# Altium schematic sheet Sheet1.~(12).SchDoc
size A; SheetNumber: 1; SheetTotal: 1
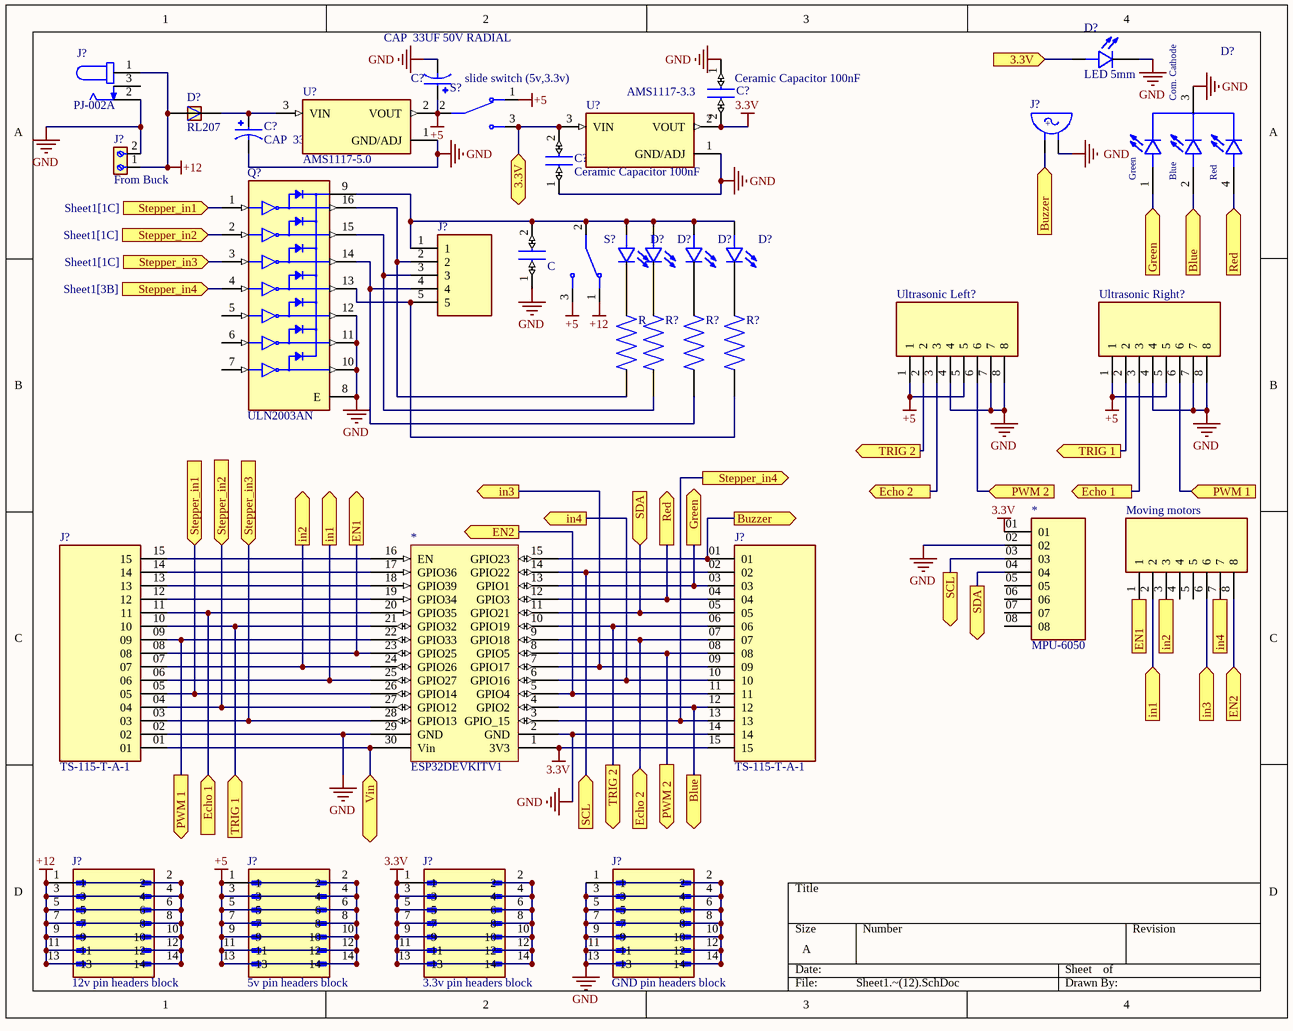
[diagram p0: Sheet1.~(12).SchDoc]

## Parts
(Parts that share a designator on the sheet are numbered #1, #2 ... from top to bottom, then left to right.)
*#1  MPU-6050  [MPU-6050]
*#2  ESP32DEVKITV1  [ESP32DEVKITV1]
C  Ceramic Capacitor 100nF  [C320C]  (value not drawn)
C?#1  Ceramic Capacitor 100nF  [C320C]
C?#2  CAP  33UF 50V RADIAL  [CAP  33UF 50V RADIAL]
C?#3  CAP  33UF 50V RADIAL  [CAP  33UF 50V RADIAL]
C?#4  Ceramic Capacitor 100nF  [C320C]
D?#1  LED 5mm  [LED 5mm]
D?#2  RL207  [DIOAD1300W80L670D310]
D?#3  common cathode  [LED RGB 5mm]  (value not drawn)
D?#4  LED 5mm  [LED 5mm]  (value not drawn)
D?#5  LED 5mm  [LED 5mm]  (value not drawn)
D?#6  LED 5mm  [LED 5mm]  (value not drawn)
D?#7  LED 5mm  [LED 5mm]  (value not drawn)
J?#1  PJ-002A  [CUI_PJ-002A]
J?#2  WST-1205S  [WST-1205S]  (value not drawn)
J?#3  From Buck  [691213510002]
J?#4  Pin hreader 5 pins  [Pin hreader 5 pins]  (value not drawn)
J?#5  TS-115-T-A-1  [SAMTEC_TS-115-T-A-1]
J?#6  TS-115-T-A-1  [SAMTEC_TS-115-T-A-1]
J?#7  12v pin headers block  [AMPHENOL_52601-S14-4LF]
J?#8  5v pin headers block  [AMPHENOL_52601-S14-4LF]
J?#9  3.3v pin headers block  [AMPHENOL_52601-S14-4LF]
J?#10  GND pin headers block  [AMPHENOL_52601-S14-4LF]
Moving_motors  Pin header female block 8 pin  [Pin header female block 8 pin]  (value not drawn)
Q?  ULN2003AN  [DIP794W45P254L1969H508Q16]
R  Resistor  [RESAD700W45L350D185]  (value not drawn)
R?#1  Resistor  [RESAD700W45L350D185]  (value not drawn)
R?#2  Resistor  [RESAD700W45L350D185]  (value not drawn)
R?#3  Resistor  [RESAD700W45L350D185]  (value not drawn)
S?#1  slide switch (5v,3.3v)  [SW_EG1206]
S?#2  Slide switch  [Slide switch]  (value not drawn)
U?#1  AMS1117-5.0  [SOT229P700X180-4N]
U?#2  AMS1117-3.3  [SOT229P700X180-4N]
Ultrasonic_Left?  Pin header female block 8 pin  [Pin header female block 8 pin]  (value not drawn)
Ultrasonic_Right?  Pin header female block 8 pin  [Pin header female block 8 pin]  (value not drawn)

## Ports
3.3V (bidir, see Sheet1[4A]), 3.3V (in, see Sheet1[2A]), Blue (in, see Sheet1[3D]), Blue (out, see Sheet1[4B]), Buzzer (in, see Sheet1[3C]), Buzzer (out, see Sheet1[4A]), Echo 1 (in, see Sheet1[4B]), Echo 1 (out, see Sheet1[1D]), Echo 2 (in, see Sheet1[3B]), Echo 2 (out, see Sheet1[2D]), EN1 (in, see Sheet1[2C]), EN1 (out, see Sheet1[4C]), EN2 (in, see Sheet1[2C]), EN2 (out, see Sheet1[4C]), Green (in, see Sheet1[3C]), Green (out, see Sheet1[4B]), in1 (in, see Sheet1[2C]), in1 (out, see Sheet1[4C]), in2 (in, see Sheet1[1C]), in2 (out, see Sheet1[4C]), in3 (in, see Sheet1[2B]), in3 (out, see Sheet1[4C]), in4 (in, see Sheet1[2C]), in4 (out, see Sheet1[4C]), PWM 1 (in, see Sheet1[1D]), PWM 1 (out, see Sheet1[4B]), PWM 2 (in, see Sheet1[3D]), PWM 2 (out, see Sheet1[4B]), Red (in, see Sheet1[3C]), Red (out, see Sheet1[4B]), SCL (in, see Sheet1[3C]), SCL (out, see Sheet1[2D]), SDA (in, see Sheet1[4C]), SDA (out, see Sheet1[2C]), Stepper_in1 (in, see Sheet1[1A]), Stepper_in1 (in, see Sheet1[1C]), Stepper_in2 (in, see Sheet1[1A]), Stepper_in2 (in, see Sheet1[1C]), Stepper_in3 (in, see Sheet1[1B]), Stepper_in3 (in, see Sheet1[1C]), Stepper_in4 (in, see Sheet1[3B]), Stepper_in4 (out, see Sheet1[1B]), TRIG 1 (in, see Sheet1[4B]), TRIG 1 (out, see Sheet1[1D]), TRIG 2 (out, see Sheet1[2D]), TRIG 2 (out, see Sheet1[3B]), Vin (bidir)

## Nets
3.3V: *#1.01 *#2.1(3V3) C?#1.2 J?#6.15 J?#9.1 J?#9.2 J?#9.3 J?#9.4 J?#9.5 J?#9.6 J?#9.7 J?#9.8 J?#9.9 J?#9.10 J?#9.11 J?#9.12 J?#9.13 J?#9.14 U?#2.2(VOUT)
 GND: *#1.02 *#2.2(GND) *#2.29(GND) C.1 C?#1.1 C?#2.N C?#3.N C?#4.1 D?#1.C D?#3.3(Com._Cathode) J?#1.2 J?#2.NEG J?#3.2 J?#5.02 J?#6.14 J?#10.1 J?#10.2 J?#10.3 J?#10.4 J?#10.5 J?#10.6 J?#10.7 J?#10.8 J?#10.9 J?#10.10 J?#10.11 J?#10.12 J?#10.13 J?#10.14 Q?.8(E) Q?.10(7C) Q?.11(6C) Q?.12(5C) U?#1.1(GND/ADJ) U?#2.1(GND/ADJ) Ultrasonic_Left?.4 Ultrasonic_Left?.7 Ultrasonic_Left?.8 Ultrasonic_Right?.4 Ultrasonic_Right?.7 Ultrasonic_Right?.8  [also labelled GND]
+5: C?#2.P J?#8.1 J?#8.2 J?#8.3 J?#8.4 J?#8.5 J?#8.6 J?#8.7 J?#8.8 J?#8.9 J?#8.10 J?#8.11 J?#8.12 J?#8.13 J?#8.14 S?#1.1 S?#1.2 S?#2.3 U?#1.2(VOUT) Ultrasonic_Left?.1 Ultrasonic_Left?.5 Ultrasonic_Right?.1 Ultrasonic_Right?.5
+12: D?#2.A J?#1.1 J?#3.1 J?#7.1 J?#7.2 J?#7.3 J?#7.4 J?#7.5 J?#7.6 J?#7.7 J?#7.8 J?#7.9 J?#7.10 J?#7.11 J?#7.12 J?#7.13 J?#7.14 S?#2.1
3.3V: C?#4.2 D?#1.A S?#1.3 U?#2.3(VIN) ; port 3.3V  [a separate net that carries the same name]
Blue: *#2.4(GPIO2) D?#3.2(BLUE) J?#6.12 ; port Blue
Buzzer: *#2.15(GPIO23) J?#2.POS J?#6.01 ; port Buzzer
Echo 1: *#2.20(GPIO35) J?#5.11 Ultrasonic_Right?.3 ; port Echo 1
Echo 2: *#2.9(GPIO18) J?#6.07 Ultrasonic_Left?.3 ; port Echo 2
EN1: *#2.23(GPIO25) J?#5.08 Moving_motors.1 ; port EN1
EN2: *#2.5(GPIO4) J?#6.11 Moving_motors.8 ; port EN2
Green: *#2.13(GPIO1) D?#3.1(Green) J?#6.03 ; port Green
in1: *#2.25(GPIO27) J?#5.06 Moving_motors.2 ; port in1
in2: *#2.24(GPIO26) J?#5.07 Moving_motors.3 ; port in2
in3: *#2.7(GPIO17) J?#6.09 Moving_motors.6 ; port in3
in4: *#2.6(GPIO16) J?#6.10 Moving_motors.7 ; port in4
PWM 1: *#2.22(GPIO33) J?#5.09 Ultrasonic_Right?.6 ; port PWM 1
PWM 2: *#2.8(GPIO5) J?#6.08 Ultrasonic_Left?.6 ; port PWM 2
Red: *#2.12(GPIO3) D?#3.4(Red) J?#6.04 ; port Red
SCL: *#1.03 *#2.14(GPIO22) J?#6.02 ; port SCL
SDA: *#1.04 *#2.11(GPIO21) J?#6.05 ; port SDA
Stepper_in1: *#2.26(GPIO14) J?#5.05 Q?.1(1B) ; port Stepper_in1
Stepper_in2: *#2.27(GPIO12) J?#5.04 Q?.2(2B) ; port Stepper_in2
Stepper_in3: *#2.28(GPIO13) J?#5.03 Q?.3(3B) ; port Stepper_in3
Stepper_in4: *#2.3(GPIO_15) J?#6.13 Q?.4(4B) ; port Stepper_in4
TRIG 1: *#2.21(GPIO32) J?#5.10 Ultrasonic_Right?.2 ; port TRIG 1
TRIG 2: *#2.10(GPIO19) J?#6.06 Ultrasonic_Left?.2 ; port TRIG 2
Vin: *#2.30(Vin) J?#5.01 ; port Vin
Net*#2_16: *#2.16(EN) J?#5.15
Net*#2_17: *#2.17(GPIO36) J?#5.14
Net*#2_18: *#2.18(GPIO39) J?#5.13
Net*#2_19: *#2.19(GPIO34) J?#5.12
NetC?#3_P: C?#3.P D?#2.C U?#1.3(VIN)
NetC_2: C.2 D?#4.A D?#5.A D?#6.A D?#7.A J?#4.1 Q?.9(COM) S?#2.2
NetD?#4_C: D?#4.C R.1
NetD?#5_C: D?#5.C R?#1.1
NetD?#6_C: D?#6.C R?#2.1
NetD?#7_C: D?#7.C R?#3.1
NetJ?#4_2: J?#4.2 Q?.16(1C) R.2
NetJ?#4_3: J?#4.3 Q?.15(2C) R?#1.2
NetJ?#4_4: J?#4.4 Q?.14(3C) R?#2.2
NetJ?#4_5: J?#4.5 Q?.13(4C) R?#3.2

Not connected (* = marked no-connect by the designer): *#1 05 06 07 08; J?#1 3; Moving_motors 4 5; Q? 5(5B) 6(6B) 7(7B)

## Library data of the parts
C C?#1 C?#4 = Ceramic Capacitor 100nF: 0.1ÂµF Â±20% 50V Ceramic Capacitor Z5U Radial; MF: KEMET; MP: C320C104M5U5TA
C?#2 C?#3 = CAP  33UF 50V RADIAL: NHG-A; MF: {'manufacturer': u'Panasonic'}; MP: ECA1HHG330I
D?#1 D?#4-D?#7 = LED 5mm: Red 623nm LED Indication - Discrete 1.9V Radial; MF: {'manufacturer': u'Wurth Elektronik'}; MP: 151054RS03000
D?#2 = RL207: Semiconductors and Actives, Power Diodes, Discretes (diodes, transistors, thyristors ...), Diodes; MF: {'manufacturer': u'Diodes Inc.'}
D?#3 = LED RGB 5mm: MF: {'manufacturer': u'Kingbright'}; MP: WP154A4SUREQBFZGC
J?#1 = PJ-002A: 2.0 mm Center Pin, 2.5 A, Right Angle, Through Hole, Dc Power Jack Connector; MF: {'manufacturer': u'CUI Devices'}
J?#2 = WST-1205S: BUZZER 2.3KHZ 4-6VDC; MF: {'manufacturer': u'Soberton Inc.'}
J?#3 = Terminal Block: 2 Position Wire to Board Terminal Block Horizontal with Board 0.200 (5.08mm) Through Hole; MF: Wurth Electronics
J?#4 = Pin hreader 5 pins: MF: {'manufacturer': u'TE Connectivity'}; MP: 2355181-5
J?#5 J?#6 = TS-115-T-A-1: MF: {'manufacturer': u'Samtec'}
J?#7-J?#10 = 52601-S14-4LF: MF: {'manufacturer': u'Amphenol ICC (FCI)'}
Moving_motors Ultrasonic_Left? Ultrasonic_Right? = Pin header female block 8 pin: MF: {'manufacturer': u'TE Connectivity'}; MP: 5-534998-4
Q? = ULN2003AN: MF: {'manufacturer': u'Texas Instruments'}
R R?#1-R?#3 = Resistor: CFR16 5% 10K; MF: {'manufacturer': u'TE Connectivity'}; MP: 2-1623927-3
S?#1 = EG1206: MF: {'manufacturer': u'E-Switch'}
S?#2 = Slide switch: MF: {'manufacturer': u'E-Switch'}; MP: EG1206
U?#1 = AMS1117-5.0: MF: {'manufacturer': u'Advanced Monolithic Systems'}
U?#2 = AMS1117-3.3: MF: {'manufacturer': u'Advanced Monolithic Systems'}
